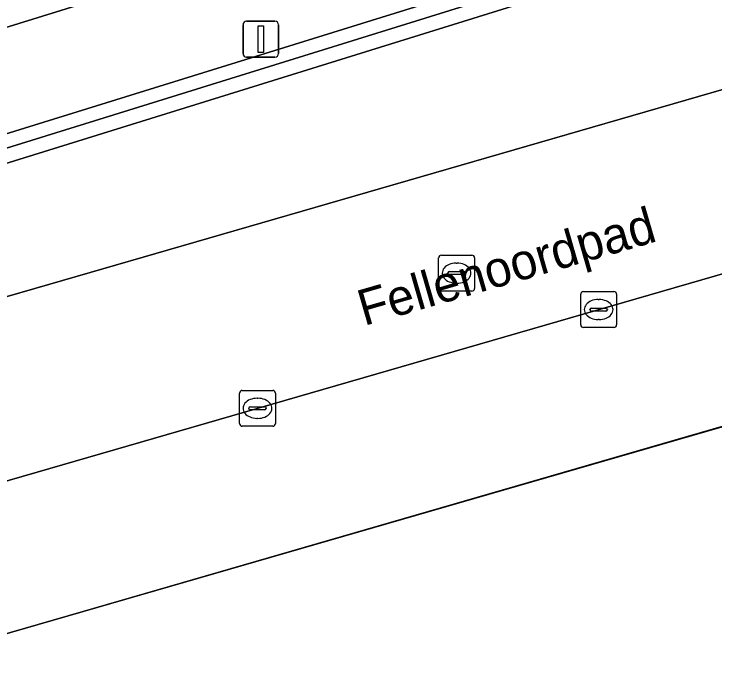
# Model space of a CAD drawing. Extents: x 160806 to 161707, y 383696 to 384148.
# Drawn here: x 161162.41 to 161181.96, y 383824.68 to 383842.89 of the extents above; entities that cross this region are included whole.
import ezdxf

# ---------------------------------------------------------------- set-up
doc = ezdxf.new("R2010")
doc.units = 0
for name, color, linetype in [('IMGEO_Berm_groen', 7, 'Continuous'), ('IMGEO_Fietspad_open', 7, 'Continuous'), ('IMGEO_Groenvoorziening', 7, 'Continuous'), ('IMGEO_Kolk', 7, 'Continuous'), ('IMGEO_Lichtmast', 7, 'Continuous'), ('IMGEO_Muur', 7, 'Continuous'), ('IMGEO_Openbare_ruimte_label', 7, 'Continuous'), ('IMGEO_OVBaan_gesloten', 7, 'Continuous'), ('IMGEO_Pand', 7, 'Continuous'), ('IMGEO_Pand_overbouw', 7, 'Continuous'), ('IMGEO_Rioolput', 7, 'Continuous'), ('IMGEO_Voetpad_open', 7, 'Continuous')]:
    doc.layers.add(name, color=color, linetype=linetype)

msp = doc.modelspace()

# ---------------------------------------------------------------- linework, layer by layer
at = {"layer": 'IMGEO_Berm_groen'}
msp.add_lwpolyline([(161232.169, 383864.306), (161220.786, 383860.784), (161197.293, 383853.461), (161167.281, 383844.11), (161156.084, 383840.634), (161156.904, 383837.916), (161229.219, 383860.361)], dxfattribs=at)
at = {"layer": 'IMGEO_Fietspad_open'}
msp.add_lwpolyline([(161233.944, 383854.997), (161230.53, 383854.241), (161222.537, 383852.474), (161163.411, 383835.363), (161161.786, 383834.896), (161160.518, 383834.532), (161157.878, 383833.775), (161159.382, 383829.051), (161223.387, 383847.584)], dxfattribs=at)
at = {"layer": 'IMGEO_Groenvoorziening'}
msp.add_lwpolyline([(161227.057, 383858.887), (161226.937, 383859.268), (161157.726, 383837.763), (161157.851, 383837.383), (161160.918, 383838.336)], close=True, dxfattribs=at)
at = {"layer": 'IMGEO_Kolk'}
for p, q in [((161178.288, 383835.15), (161179.14, 383835.15)), ((161178.213, 383834.224), (161178.213, 383835.076)), ((161179.214, 383835.076), (161179.214, 383834.224)), ((161178.701, 383834.93), (161178.726, 383834.93)), ((161178.472, 383834.644), (161178.472, 383834.656)), ((161178.91, 383834.607), (161178.512, 383834.607)), ((161178.515, 383834.693), (161178.913, 383834.693)), ((161178.956, 383834.656), (161178.956, 383834.644)), ((161178.724, 383834.37), (161178.699, 383834.37)), ((161179.14, 383834.15), (161178.288, 383834.15)), ((161168.697, 383831.47), (161168.697, 383832.322)), ((161168.772, 383832.396), (161169.624, 383832.396)), ((161169.698, 383832.322), (161169.698, 383831.47)), ((161169.185, 383832.176), (161169.21, 383832.176)), ((161168.956, 383831.89), (161168.956, 383831.902)), ((161169.394, 383831.853), (161168.996, 383831.853)), ((161168.999, 383831.939), (161169.397, 383831.939)), ((161169.44, 383831.902), (161169.44, 383831.89)), ((161169.208, 383831.616), (161169.183, 383831.616)), ((161169.624, 383831.396), (161168.772, 383831.396))]:
    msp.add_line(p, q, dxfattribs=at)
for points in [[(161178.288, 383835.15), (161179.14, 383835.15)], [(161178.213, 383834.224), (161178.213, 383835.076)], [(161179.214, 383835.076), (161179.214, 383834.224)], [(161179.14, 383834.15), (161178.288, 383834.15)], [(161168.697, 383831.47), (161168.697, 383832.322)], [(161168.772, 383832.396), (161169.624, 383832.396)], [(161169.698, 383832.322), (161169.698, 383831.47)], [(161169.624, 383831.396), (161168.772, 383831.396)]]:
    msp.add_lwpolyline(points, dxfattribs=at)
for centre, radius, start, end in [((161178.29, 383835.074), 0.0765, 91.552, 178.448), ((161178.29, 383835.074), 0.0765, 91.552, 178.448), ((161179.138, 383835.074), 0.0765, 1.552, 88.448), ((161179.138, 383835.074), 0.0765, 1.552, 88.448), ((161178.512, 383834.653), 0.0403, 85.8775, 175.7526), ((161178.509, 383834.643), 0.0366, 178.938, 274.7102), ((161178.913, 383834.65), 0.043, 264.8664, 352.4533), ((161178.917, 383834.655), 0.0386, 1.7309, 96.639), ((161178.29, 383834.226), 0.0765, 181.552, 268.448), ((161178.29, 383834.226), 0.0765, 181.552, 268.448), ((161179.138, 383834.226), 0.0765, 271.552, 358.448), ((161179.138, 383834.226), 0.0765, 271.552, 358.448), ((161168.774, 383832.32), 0.0765, 91.552, 178.448), ((161168.774, 383832.32), 0.0765, 91.552, 178.448), ((161169.622, 383832.32), 0.0765, 1.552, 88.448), ((161169.622, 383832.32), 0.0765, 1.552, 88.448), ((161168.996, 383831.899), 0.0403, 85.8775, 175.7526), ((161168.993, 383831.889), 0.0366, 178.938, 274.7102), ((161169.397, 383831.896), 0.043, 264.8664, 352.4533), ((161169.401, 383831.901), 0.0386, 1.7309, 96.639), ((161168.774, 383831.472), 0.0765, 181.552, 268.448), ((161168.774, 383831.472), 0.0765, 181.552, 268.448), ((161169.622, 383831.472), 0.0765, 271.552, 358.448), ((161169.622, 383831.472), 0.0765, 271.552, 358.448)]:
    msp.add_arc(centre, radius, start, end, dxfattribs=at)
for centre, major_axis, ratio, start_param, end_param in [((161178.7, 383834.65), (-0.387, 0.002), 0.722429, 4.712389, 7.853982), ((161178.725, 383834.65), (-0.39, 0.002), 0.717154, 1.570796, 4.712389), ((161169.184, 383831.896), (-0.387, 0.002), 0.722429, 4.712389, 7.853982), ((161169.209, 383831.896), (-0.39, 0.002), 0.717154, 1.570796, 4.712389)]:
    msp.add_ellipse(centre, major_axis=major_axis, ratio=ratio, start_param=start_param, end_param=end_param, dxfattribs=at)
at = {"layer": 'IMGEO_Lichtmast'}
for p, q in [((161168.795, 383841.794), (161168.795, 383842.594)), ((161168.795, 383842.594), (161168.795, 383841.794)), ((161168.895, 383842.694), (161169.685, 383842.694)), ((161169.685, 383842.694), (161168.895, 383842.694)), ((161169.785, 383842.594), (161169.785, 383841.794)), ((161169.785, 383841.794), (161169.785, 383842.594)), ((161169.685, 383841.694), (161168.895, 383841.694)), ((161168.895, 383841.694), (161169.685, 383841.694))]:
    msp.add_line(p, q, dxfattribs=at)
msp.add_lwpolyline([(161169.215, 383842.569), (161169.365, 383842.569), (161169.365, 383841.819), (161169.215, 383841.819), (161169.215, 383842.569)], dxfattribs=at)
for centre, start, end in [((161168.895, 383842.594), 90, 180), ((161168.895, 383842.594), 90, 180), ((161169.685, 383842.594), 0, 90), ((161169.685, 383842.594), 360, 90), ((161168.895, 383841.794), 180, 270), ((161168.895, 383841.794), 180, 270), ((161169.685, 383841.794), 270, 0), ((161169.685, 383841.794), 270, 0)]:
    msp.add_arc(centre, 0.1, start, end, dxfattribs=at)
at = {"layer": 'IMGEO_Muur'}
msp.add_lwpolyline([(161230.728, 383855.33), (161229.219, 383860.361), (161156.904, 383837.916), (161157.016, 383837.543), (161157.726, 383837.763), (161226.937, 383859.268), (161228.848, 383859.862), (161230.248, 383855.182)], close=True, dxfattribs=at)
at = {"layer": 'IMGEO_OVBaan_gesloten'}
msp.add_lwpolyline([(161220.786, 383860.784), (161232.169, 383864.306), (161232.936, 383864.528), (161231.893, 383867.665), (161231.771, 383868.031), (161217.778, 383863.592), (161209.997, 383861.169), (161192.607, 383855.742), (161162.9, 383846.464), (161159.136, 383845.321), (161157.213, 383844.802), (161155.744, 383844.438), (161154.991, 383844.26), (161156.084, 383840.634), (161167.281, 383844.11), (161197.293, 383853.461)], close=True, dxfattribs=at)
at = {"layer": 'IMGEO_Pand'}
msp.add_lwpolyline([(161221.311, 383832.189), (161220.955, 383833.419), (161219.851, 383837.235), (161216.277, 383836.232), (161215.039, 383840.515), (161214.94, 383840.857), (161157.832, 383824.35), (161159.26, 383819.473), (161155.555, 383818.417), (161155.737, 383817.796), (161156.438, 383818.002), (161166.655, 383782.656), (161165.953, 383782.453), (161166.564, 383780.339), (161167.861, 383780.714)], dxfattribs=at)
at = {"layer": 'IMGEO_Pand_overbouw'}
msp.add_lwpolyline([(161244.397, 383752.352), (161218.72, 383841.978), (161097.833, 383806.973), (161123.797, 383717.365)], close=True, dxfattribs=at)
at = {"layer": 'IMGEO_Rioolput'}
for p, q in [((161174.326, 383836.168), (161175.178, 383836.168)), ((161174.251, 383835.242), (161174.251, 383836.094)), ((161174.739, 383835.948), (161174.764, 383835.948)), ((161175.252, 383836.094), (161175.252, 383835.242)), ((161174.51, 383835.662), (161174.51, 383835.674)), ((161174.948, 383835.625), (161174.55, 383835.625)), ((161174.553, 383835.711), (161174.951, 383835.711)), ((161174.994, 383835.674), (161174.994, 383835.662)), ((161174.762, 383835.388), (161174.737, 383835.388)), ((161175.178, 383835.168), (161174.326, 383835.168))]:
    msp.add_line(p, q, dxfattribs=at)
for points in [[(161174.326, 383836.168), (161175.178, 383836.168)], [(161174.251, 383835.242), (161174.251, 383836.094)], [(161175.252, 383836.094), (161175.252, 383835.242)], [(161175.178, 383835.168), (161174.326, 383835.168)]]:
    msp.add_lwpolyline(points, dxfattribs=at)
for centre, radius, start, end in [((161174.328, 383836.092), 0.0765, 91.552, 178.448), ((161174.328, 383836.092), 0.0765, 91.552, 178.448), ((161175.176, 383836.092), 0.0765, 1.552, 88.448), ((161175.176, 383836.092), 0.0765, 1.552, 88.448), ((161174.55, 383835.671), 0.0403, 85.8775, 175.7526), ((161174.547, 383835.661), 0.0366, 178.938, 274.7102), ((161174.951, 383835.668), 0.043, 264.8664, 352.4533), ((161174.955, 383835.673), 0.0386, 1.7309, 96.639), ((161174.328, 383835.244), 0.0765, 181.552, 268.448), ((161174.328, 383835.244), 0.0765, 181.552, 268.448), ((161175.176, 383835.244), 0.0765, 271.552, 358.448), ((161175.176, 383835.244), 0.0765, 271.552, 358.448)]:
    msp.add_arc(centre, radius, start, end, dxfattribs=at)
for centre, major_axis, ratio, start_param, end_param in [((161174.738, 383835.668), (-0.387, 0.002), 0.722429, 4.712389, 7.853982), ((161174.763, 383835.668), (-0.39, 0.002), 0.717154, 1.570796, 4.712389)]:
    msp.add_ellipse(centre, major_axis=major_axis, ratio=ratio, start_param=start_param, end_param=end_param, dxfattribs=at)
at = {"layer": 'IMGEO_Voetpad_open'}
msp.add_lwpolyline([(161222.537, 383852.474), (161230.53, 383854.241), (161233.944, 383854.997), (161233.61, 383856.219), (161230.728, 383855.33), (161230.248, 383855.182), (161228.848, 383859.862), (161226.937, 383859.268), (161227.057, 383858.887), (161160.918, 383838.336), (161161.786, 383834.896), (161163.411, 383835.363)], close=True, dxfattribs=at)
for points in [[(161223.387, 383847.584), (161159.382, 383829.051), (161155.557, 383827.944), (161150.139, 383826.375), (161147.684, 383825.664), (161145.931, 383825.141), (161140.997, 383823.669), (161139.325, 383823.149), (161139.098, 383823.078), (161130.359, 383820.358), (161130.105, 383820.279), (161109.484, 383813.862), (161096.549, 383808.578)], [(161140.252, 383820.19), (161145.264, 383821.735), (161145.317, 383821.577), (161145.38, 383821.389), (161145.189, 383821.329), (161146.119, 383818.112), (161147.904, 383818.638), (161147.266, 383821.092), (161148.092, 383821.328), (161153.492, 383823.019), (161154.142, 383823.222), (161157.832, 383824.35), (161214.94, 383840.857)]]:
    msp.add_lwpolyline(points, dxfattribs=at)

# ---------------------------------------------------------------- texts
at = {"layer": 'IMGEO_Openbare_ruimte_label'}
msp.add_text('Fellenoordpad', height=1, rotation=16.1342, dxfattribs=at).set_placement((161172.17, 383834.19))

doc.saveas('drawing.dxf')
